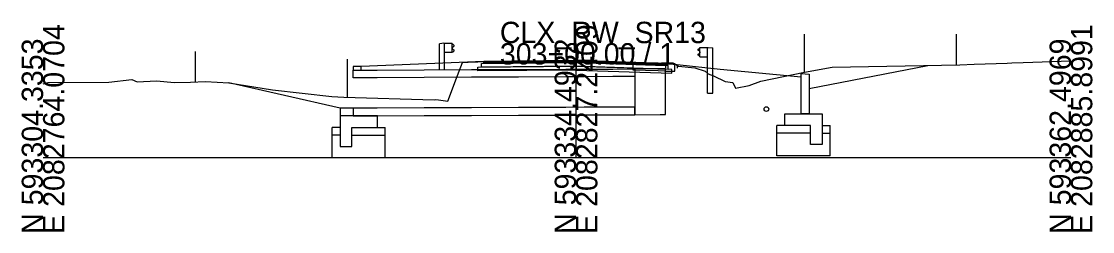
# Model space of a CAD drawing. Extents: x -26 to 2138, y -10 to 4518.
# Drawn here: x 997.2 to 1137.8, y 490.3 to 517.8 of the extents above; entities that cross this region are included whole.
import ezdxf

# ---------------------------------------------------------------- set-up
doc = ezdxf.new("R2010")
doc.units = 0
for name, color, linetype in [('DR_P_Erosion_Control', 7, 'Continuous'), ('GK_Cells', 7, 'Continuous'), ('MD_P_Surface_Aggregate_Base', 7, 'Continuous'), ('MD_P_Surface_Asphalt_Concrete_Base', 7, 'Continuous'), ('MD_P_Surface_Asphalt_Concrete_Intermediate_Course', 7, 'Continuous'), ('MD_P_Surface_Asphalt_Concrete_Surface_Course', 7, 'Continuous'), ('MD_P_Surface_Non-Reinforced_Concrete_Pavement', 7, 'Continuous'), ('MD_X_Asphalt_Pavement', 7, 'Continuous'), ('PV_P_EOP', 7, 'Continuous'), ('RD_P_Cells', 7, 'Continuous'), ('RW_P_Esmt_SH', 7, 'Continuous'), ('RW_X_Esmt_SH', 7, 'Continuous'), ('SC_Scratch1', 7, 'Continuous'), ('UT_X_Water', 7, 'Continuous'), ('XS_P_Excavation_Limits', 7, 'Continuous'), ('XS_P_Finished_Grade', 7, 'Continuous'), ('XS_X_Ground_Line', 7, 'Continuous')]:
    doc.layers.add(name, color=color, linetype=linetype)

msp = doc.modelspace()

# ---------------------------------------------------------------- linework, layer by layer
at = {"layer": 'DR_P_Erosion_Control'}
for p, q in [((1039.01, 506.46), (1024.38, 509.8)), ((1040.73, 506.46), (1039.01, 506.46)), ((1039.01, 506.46), (1039.01, 505.46))]:
    msp.add_line(p, q, dxfattribs=at)
at = {"layer": 'GK_Cells'}
for p, q in [((1070, 500), (1070, 515)), ((1000, 500), (1070, 500)), ((1070, 500), (1135, 500))]:
    msp.add_line(p, q, dxfattribs=at)
at = {"layer": 'MD_P_Surface_Aggregate_Base'}
for points in [[(1070, 511.98), (1070, 511.48), (1057.08, 511.35), (1057.08, 511.85), (1070, 511.98)], [(1070, 511.98), (1070, 511.48), (1082.6, 511.05), (1082.6, 511.55), (1070, 511.98)]]:
    msp.add_lwpolyline(points, dxfattribs=at)
at = {"layer": 'MD_P_Surface_Asphalt_Concrete_Base'}
for points in [[(1070, 512.48), (1070, 511.98), (1057.58, 511.85), (1057.58, 512.35), (1070, 512.48)], [(1070, 512.48), (1070, 511.98), (1082.1, 511.57), (1082.1, 512.07), (1081.77, 512.08), (1070, 512.48)]]:
    msp.add_lwpolyline(points, dxfattribs=at)
at = {"layer": 'MD_P_Surface_Asphalt_Concrete_Intermediate_Course'}
for points in [[(1070, 512.62), (1070, 512.48), (1057.91, 512.36), (1057.91, 512.5), (1070, 512.62)], [(1070, 512.62), (1070, 512.48), (1081.77, 512.08), (1081.77, 512.23), (1070, 512.62)]]:
    msp.add_lwpolyline(points, dxfattribs=at)
at = {"layer": 'MD_P_Surface_Asphalt_Concrete_Surface_Course'}
for points in [[(1070, 512.73), (1070, 512.62), (1057.91, 512.5), (1057.91, 512.61), (1070, 512.73)], [(1070, 512.73), (1070, 512.62), (1081.77, 512.23), (1081.77, 512.33), (1070, 512.73)]]:
    msp.add_lwpolyline(points, dxfattribs=at)
at = {"layer": 'MD_P_Surface_Non-Reinforced_Concrete_Pavement'}
for points in [[(1040.73, 511.46), (1041.76, 511.46), (1041.76, 511.96), (1040.73, 511.96), (1040.73, 511.46)], [(1077.72, 511.62), (1077.72, 510.62), (1074.84, 510.61), (1071.08, 510.59), (1068.64, 510.58), (1062.45, 510.55), (1056.25, 510.53), (1050.06, 510.5), (1043.87, 510.47), (1040.73, 510.46), (1040.73, 511.46), (1043.87, 511.47), (1050.06, 511.5), (1056.25, 511.53), (1062.45, 511.55), (1068.64, 511.58), (1071.08, 511.59), (1074.84, 511.61), (1077.72, 511.62)], [(1081.75, 505.64), (1081.75, 511.64), (1081.03, 511.64), (1077.72, 511.62), (1077.72, 505.62), (1081.03, 505.64), (1081.75, 505.64)], [(1100.6, 505.72), (1099.57, 505.72), (1099.57, 511), (1100.6, 510.93), (1100.6, 505.72)], [(1077.72, 505.62), (1077.72, 506.62), (1074.84, 506.61), (1071.08, 506.59), (1068.64, 506.58), (1062.45, 506.55), (1056.25, 506.53), (1053.56, 506.52), (1050.06, 506.5), (1043.87, 506.47), (1040.73, 506.46), (1040.73, 505.46), (1043.87, 505.47), (1050.06, 505.5), (1056.25, 505.53), (1062.45, 505.55), (1068.64, 505.58), (1071.08, 505.59), (1074.84, 505.61), (1077.72, 505.62)], [(1039.01, 505.46), (1039.01, 504.34), (1039.01, 501.46), (1040.14, 501.46), (1040.56, 501.46), (1040.56, 501.72), (1040.56, 503.96), (1042.64, 503.96), (1043.91, 503.96), (1043.91, 505.37), (1043.91, 505.46), (1040.14, 505.46), (1039.01, 505.46)], [(1102.32, 505.72), (1102.32, 502.62), (1102.32, 501.72), (1101.76, 501.72), (1100.78, 501.72), (1100.78, 502.7), (1100.78, 504.22), (1099.2, 504.22), (1098.23, 504.22), (1097.42, 504.22), (1097.42, 505.06), (1097.42, 505.72), (1099.2, 505.72), (1102.32, 505.72)]]:
    msp.add_lwpolyline(points, dxfattribs=at)
at = {"layer": 'MD_X_Asphalt_Pavement'}
msp.add_lwpolyline([(1077.45, 512.48), (1077.45, 511.52), (1080.8, 511.42), (1081.62, 511.36), (1081.83, 511.34), (1082.99, 511.31), (1082.99, 512.27), (1081.83, 512.3), (1081.62, 512.32), (1080.8, 512.38), (1077.45, 512.48)], dxfattribs=at)
at = {"layer": 'PV_P_EOP'}
msp.add_line((1057.91, 512.61), (1041.76, 511.96), dxfattribs=at)
at = {"layer": 'RD_P_Cells'}
for p, q in [((1052.1, 514.91), (1052.05, 514.89)), ((1052.64, 514.99), (1052.1, 514.91)), ((1052.72, 514.95), (1052.64, 514.99)), ((1053.72, 514.95), (1052.72, 514.95)), ((1052.72, 511.51), (1052.72, 514.95)), ((1053.72, 513.76), (1053.72, 514.95)), ((1052.05, 511.51), (1052.05, 514.89)), ((1053.72, 513.76), (1052.72, 513.76)), ((1053.81, 514.85), (1053.72, 514.87)), ((1053.72, 513.84), (1053.81, 513.86)), ((1053.73, 514.36), (1053.73, 514.4)), ((1053.73, 514.31), (1053.73, 514.36)), ((1053.76, 514.47), (1053.97, 514.61)), ((1053.97, 514.1), (1053.76, 514.24)), ((1053.97, 514.74), (1053.81, 514.85)), ((1053.81, 513.86), (1053.97, 513.97)), ((1086.03, 514.19), (1086.19, 514.31)), ((1086.24, 513.92), (1086.03, 514.07)), ((1086.03, 513.56), (1086.24, 513.7)), ((1086.19, 514.31), (1086.28, 514.32)), ((1086.27, 513.81), (1086.27, 513.86)), ((1086.27, 513.77), (1086.27, 513.81)), ((1086.28, 513.22), (1086.28, 514.41)), ((1086.28, 514.41), (1087.28, 514.41)), ((1087.28, 514.41), (1087.36, 514.45)), ((1087.28, 508.45), (1087.28, 514.41)), ((1087.36, 514.45), (1087.9, 514.37)), ((1087.9, 514.37), (1087.95, 514.34)), ((1087.95, 508.45), (1087.95, 514.34)), ((1086.19, 513.32), (1086.03, 513.43)), ((1086.28, 513.3), (1086.19, 513.32)), ((1086.28, 513.22), (1087.28, 513.22)), ((1087.28, 508.45), (1087.95, 508.45))]:
    msp.add_line(p, q, dxfattribs=at)
for points in [[(1053.74, 514.42), (1053.74, 514.3), (1053.73, 514.3), (1053.73, 514.42)], [(1053.74, 514.38), (1053.74, 514.33), (1053.76, 514.33), (1053.76, 514.38)], [(1086.26, 513.84), (1086.26, 513.78), (1086.24, 513.78), (1086.24, 513.84)], [(1086.26, 513.87), (1086.26, 513.75), (1086.27, 513.75), (1086.27, 513.87)]]:
    msp.add_lwpolyline(points, close=True, dxfattribs=at)
for centre, start, end in [((1053.81, 514.4), 124.962, 180), ((1053.81, 514.31), 180, 235.038), ((1053.92, 514.67), 304.962, 54.7677), ((1053.92, 514.04), 304.962, 54.7677), ((1086.08, 514.13), 125.2323, 235.038), ((1086.08, 513.49), 125.2323, 235.038), ((1086.19, 513.86), 0, 55.038), ((1086.19, 513.77), 304.962, 0)]:
    msp.add_arc(centre, 0.0781, start, end, dxfattribs=at)
at = {"layer": 'RW_P_Esmt_SH'}
for p, q in [((1119.95, 512.16), (1119.95, 516.16)), ((1020, 509.92), (1020, 513.92))]:
    msp.add_line(p, q, dxfattribs=at)
at = {"layer": 'RW_X_Esmt_SH'}
for p, q in [((1100, 511.19), (1100, 516.19)), ((1040, 507.91), (1040, 512.91))]:
    msp.add_line(p, q, dxfattribs=at)
at = {"layer": 'SC_Scratch1'}
for p, q in [((1070, 512.73), (1057.91, 512.61)), ((1070, 512.62), (1057.91, 512.5)), ((1057.91, 512.61), (1057.91, 512.36)), ((1070, 512.48), (1057.91, 512.36)), ((1070, 512.73), (1081.77, 512.33)), ((1070, 512.62), (1081.77, 512.23)), ((1070, 512.48), (1081.77, 512.08)), ((1081.77, 512.33), (1081.77, 511.71)), ((1081.77, 512.33), (1083.27, 512.18)), ((1083.27, 512.18), (1083.27, 511.71))]:
    msp.add_line(p, q, dxfattribs=at)
at = {"layer": 'UT_X_Water'}
msp.add_circle((1095, 506.36), 0.3, dxfattribs=at)
at = {"layer": 'XS_P_Excavation_Limits'}
for p, q in [((1037.97, 499.96), (1037.97, 503.96)), ((1039.01, 503.96), (1037.97, 503.96)), ((1043.91, 503.96), (1044.94, 503.96)), ((1044.94, 499.96), (1044.94, 503.96)), ((1096.39, 500.22), (1096.39, 504.22)), ((1097.42, 504.22), (1096.39, 504.22)), ((1102.32, 504.22), (1103.36, 504.22)), ((1103.36, 500.22), (1103.36, 504.22)), ((1039.01, 502.96), (1037.97, 502.96)), ((1040.56, 502.96), (1044.94, 502.96)), ((1100.78, 503.22), (1096.39, 503.22)), ((1102.32, 503.22), (1103.36, 503.22)), ((1044.94, 499.96), (1037.97, 499.96)), ((1103.36, 500.22), (1096.39, 500.22))]:
    msp.add_line(p, q, dxfattribs=at)
at = {"layer": 'XS_P_Finished_Grade'}
for p, q in [((1083.27, 512.18), (1088.95, 511.61)), ((1100.6, 509.05), (1116.21, 512.08)), ((1088.95, 511.61), (1099.57, 510.6))]:
    msp.add_line(p, q, dxfattribs=at)
at = {"layer": 'XS_X_Ground_Line'}
msp.add_lwpolyline([(1000, 509.65), (1000.69, 509.82), (1008.64, 509.87), (1011.65, 510.25), (1012.36, 509.91), (1014.92, 510.06), (1017.27, 509.86), (1019.37, 509.89), (1021.34, 509.97), (1024.38, 509.8), (1030.14, 508.89), (1037.93, 508.01), (1039.51, 507.92), (1051.35, 507.57), (1051.58, 507.6), (1051.95, 507.57), (1053.14, 507.41), (1054.41, 510.74), (1055.1, 512.47), (1055.83, 512.49), (1059.65, 512.64), (1066.62, 512.69), (1070.15, 512.73), (1077.2, 512.49), (1080.8, 512.38), (1081.83, 512.3), (1082.99, 512.27), (1083.44, 512), (1085.61, 511.77), (1086.96, 511.31), (1087.36, 510.98), (1088.04, 510.7), (1089.6, 509.96), (1090.58, 509.85), (1090.94, 509.08), (1092.73, 509.46), (1094.26, 510), (1100.01, 511.2), (1103.65, 511.83), (1120.41, 512.17), (1122.3, 512.23), (1126.64, 512.38), (1127.24, 512.4), (1128.72, 512.48), (1135, 512.67)], dxfattribs=at)

# ---------------------------------------------------------------- texts
msp.add_text('-', height=0.0001).set_placement((1000, 500))
at = {"layer": 'GK_Cells'}
for s, p in [('CLX_RW_SR13', (1060, 515)), ('303+00.00 / 1', (1060, 512.2))]:
    msp.add_text(s, height=2.8, dxfattribs=at).set_placement(p)
for s, p in [('E 2082764.0704', (1002.8, 490)), ('E 2082827.2409', (1072.8, 490)), ('E 2082885.8991', (1137.8, 490)), ('N 593304.3353', (1000, 490)), ('N 593334.4932', (1070, 490)), ('N 593362.4969', (1135, 490))]:
    msp.add_text(s, height=2.8, rotation=90, dxfattribs=at).set_placement(p)

doc.saveas('drawing.dxf')
